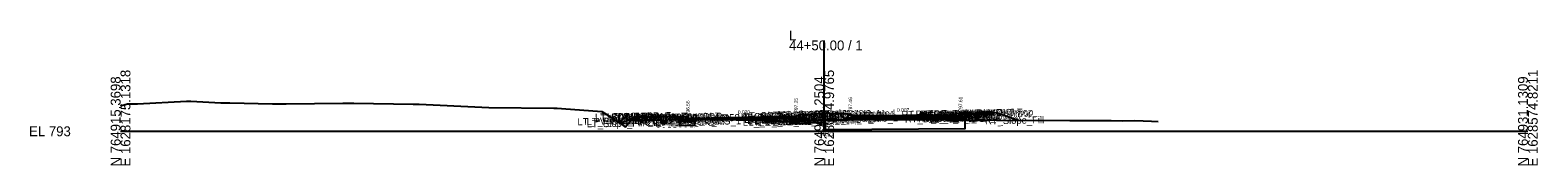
# Model space of a CAD drawing. Extents: x -26 to 4403, y -510 to 9556.
# Drawn here: x 2974.3 to 3402.8, y 4490.3 to 4528.6 of the extents above; entities that cross this region are included whole.
import ezdxf

# ---------------------------------------------------------------- set-up
doc = ezdxf.new("R2010")
doc.units = 0
for name, color, linetype in [('Default', 7, 'Continuous'), ('Exist CMT Pavement', 7, 'Continuous'), ('Exist Cross Section Cell', 7, 'Continuous'), ('Exist XS Center Line Elevation Label', 7, 'Continuous'), ('Exist XS Ground Line', 7, 'Continuous'), ('Prop CMT Conc Surface', 7, 'Continuous'), ('Prop CMT Concrete Structures', 7, 'Continuous'), ('Prop CMT Pvmt Course 1', 7, 'Continuous'), ('Prop CMT Pvmt Course 1 CG', 7, 'Continuous'), ('Prop CMT Pvmt Course 2', 7, 'Continuous'), ('Prop CMT Pvmt Course 2 Wedge', 7, 'Continuous'), ('Prop CMT Pvmt Course 3', 7, 'Continuous'), ('Prop CMT Pvmt Course 3 Wedge', 7, 'Continuous'), ('Prop CMT Pvmt Surface', 7, 'Continuous'), ('Prop CMT Shallow Undercut', 7, 'Continuous'), ('Prop CMT Shallow Undercut Boundary', 7, 'Continuous'), ('Prop CMT Slope Grass', 7, 'Continuous'), ('Prop CMT Subgrade Earthwork', 7, 'Continuous'), ('Prop CMT Undercut Boundary', 7, 'Continuous'), ('Prop XS Hydro Elevations', 7, 'Continuous'), ('Prop XS SE Text', 7, 'Continuous'), ('Prop XS Side Slope Text', 7, 'Continuous'), ('Scratch_Level_0', 7, 'Continuous')]:
    doc.layers.add(name, color=color, linetype=linetype)

msp = doc.modelspace()

# ---------------------------------------------------------------- linework, layer by layer
at = {"layer": 'Exist CMT Pavement'}
msp.add_lwpolyline([(3163.26, 4503.34), (3171.04, 4503.32), (3179.03, 4503.16), (3182.93, 4503.07), (3185.38, 4502.99), (3190.29, 4502.83)], dxfattribs=at)
at = {"layer": 'Exist Cross Section Cell'}
for p, q in [((3200, 4500), (3200, 4525.82)), ((3000, 4500), (3200, 4500)), ((3200, 4500), (3400, 4500))]:
    msp.add_line(p, q, dxfattribs=at)
at = {"layer": 'Exist XS Ground Line'}
msp.add_lwpolyline([(3000, 4507.26), (3001.98, 4507.77), (3004.81, 4507.85), (3018.76, 4508.56), (3019.94, 4508.61), (3028.49, 4508.12), (3031.03, 4508.07), (3043.17, 4507.81), (3047.06, 4507.79), (3063.19, 4508.02), (3066.31, 4507.99), (3083.2, 4507.72), (3084.88, 4507.69), (3102.72, 4506.86), (3104.71, 4506.76), (3123.12, 4506.62), (3123.71, 4506.62), (3124.11, 4506.6), (3125.33, 4506.52), (3136.82, 4505.63), (3139.26, 4504.1), (3142.46, 4501.95), (3143.03, 4501.56), (3143.53, 4501.28), (3144.92, 4503), (3159.01, 4503.34), (3159.37, 4503.35), (3160.22, 4503.35), (3171.04, 4503.32), (3179.03, 4503.16), (3182.93, 4503.07), (3185.38, 4502.99), (3190.29, 4502.83), (3192.5, 4502.88), (3198.36, 4503.2), (3200, 4503.21), (3206.75, 4503.28), (3213.59, 4503.32), (3219.88, 4503.32), (3249, 4503.16), (3269.81, 4503.1), (3281.61, 4503.05), (3284.9, 4503.01), (3288.31, 4503.04), (3293.04, 4502.89), (3294.96, 4502.83)], dxfattribs=at)
at = {"layer": 'Prop CMT Conc Surface'}
for points in [[(3153.63, 4504.2), (3148.63, 4504.3)], [(3161.25, 4503.55), (3161.25, 4504.05), (3160.75, 4504.05)], [(3191.25, 4504.23), (3192, 4504.25), (3192, 4504.41), (3192.76, 4504.66)], [(3208.19, 4504.47), (3207.44, 4504.46), (3207.44, 4504.63), (3206.68, 4504.88)], [(3236.75, 4504.67), (3238.75, 4504.61)], [(3238.75, 4504.61), (3238.75, 4505.11), (3239.25, 4505.11)], [(3243.25, 4505.2), (3248.25, 4505.3)], [(3163.25, 4503.67), (3161.25, 4503.55)]]:
    msp.add_lwpolyline(points, dxfattribs=at)
at = {"layer": 'Prop CMT Concrete Structures'}
for points in [[(3148.63, 4503.97), (3148.63, 4504.3)], [(3148.63, 4504.3), (3153.63, 4504.2)], [(3153.63, 4503.87), (3148.63, 4503.97)], [(3153.63, 4504.2), (3153.63, 4503.87)], [(3163.25, 4503.67), (3161.25, 4503.55), (3161.25, 4504.05), (3160.75, 4504.05)], [(3160.75, 4504.05), (3160.75, 4503.04), (3163.25, 4503.09)], [(3191.25, 4504.23), (3192, 4504.25), (3192, 4504.41), (3192.76, 4504.66)], [(3191.25, 4503.65), (3191.25, 4504.23)], [(3192.76, 4504.66), (3192.76, 4503.68)], [(3208.19, 4504.47), (3207.44, 4504.46), (3207.44, 4504.63), (3206.68, 4504.88)], [(3206.68, 4504.88), (3206.68, 4503.87)], [(3206.68, 4503.87), (3208.19, 4503.88)], [(3208.19, 4503.88), (3208.19, 4504.47)], [(3236.75, 4504.67), (3238.75, 4504.61), (3238.75, 4505.11), (3239.25, 4505.11)], [(3239.25, 4505.11), (3239.25, 4504.11), (3236.75, 4504.09)], [(3236.75, 4504.09), (3236.75, 4504.67)], [(3248.25, 4505.3), (3243.25, 4505.2)], [(3243.25, 4505.2), (3243.25, 4504.87)], [(3243.25, 4504.87), (3248.25, 4504.97)], [(3248.25, 4504.97), (3248.25, 4505.3)], [(3163.25, 4503.09), (3163.25, 4503.67)], [(3192.76, 4503.68), (3191.25, 4503.65)]]:
    msp.add_lwpolyline(points, dxfattribs=at)
at = {"layer": 'Prop CMT Pvmt Course 1'}
for points in [[(3191.25, 4504.23), (3163.25, 4503.67)], [(3163.25, 4503.42), (3190.29, 4503.96), (3191.25, 4503.98)], [(3191.25, 4503.98), (3191.25, 4504.23)], [(3208.19, 4504.47), (3236.75, 4504.67)], [(3208.19, 4504.22), (3208.19, 4504.47)], [(3236.75, 4504.42), (3208.19, 4504.22)], [(3208.19, 4504.22), (3208.19, 4504.22), (3208.19, 4504.22)], [(3236.75, 4504.67), (3236.75, 4504.42)], [(3163.25, 4503.67), (3163.25, 4503.42), (3163.25, 4503.42)]]:
    msp.add_lwpolyline(points, dxfattribs=at)
at = {"layer": 'Prop CMT Pvmt Course 1 CG'}
for points in [[(3208.19, 4503.88), (3206.18, 4503.87), (3205.84, 4503.53)], [(3208.19, 4503.55), (3208.19, 4503.88)], [(3236.75, 4504.09), (3239.75, 4504.11), (3240.08, 4503.78)], [(3236.75, 4503.76), (3236.75, 4504.09)], [(3163.25, 4503.09), (3160.25, 4503.03), (3159.91, 4502.69)], [(3159.91, 4502.69), (3163.25, 4502.76)], [(3163.25, 4502.76), (3163.25, 4503.09)], [(3191.25, 4503.65), (3193.26, 4503.69), (3193.59, 4503.36)], [(3191.25, 4503.32), (3191.25, 4503.65)], [(3193.59, 4503.36), (3191.25, 4503.32)], [(3205.84, 4503.53), (3208.19, 4503.55)], [(3240.08, 4503.78), (3236.75, 4503.76)]]:
    msp.add_lwpolyline(points, dxfattribs=at)
at = {"layer": 'Prop CMT Pvmt Course 2'}
for points in [[(3191.25, 4503.98), (3190.29, 4503.96)], [(3190.29, 4503.96), (3190.29, 4503.63)], [(3191.25, 4503.65), (3191.25, 4503.98)], [(3208.19, 4504.22), (3236.75, 4504.42)], [(3208.19, 4503.88), (3208.19, 4504.22)], [(3236.75, 4504.09), (3208.19, 4503.88)], [(3236.75, 4504.42), (3236.75, 4504.09)], [(3163.25, 4503.09), (3163.25, 4503.09), (3163.25, 4503.42), (3163.25, 4503.42)], [(3163.25, 4503.42), (3163.25, 4503.09)], [(3190.29, 4503.63), (3191.25, 4503.65)]]:
    msp.add_lwpolyline(points, dxfattribs=at)
at = {"layer": 'Prop CMT Pvmt Course 2 Wedge'}
for points in [[(3163.25, 4503.42), (3171.04, 4503.58), (3179.03, 4503.74), (3182.93, 4503.82), (3185.38, 4503.87), (3190.29, 4503.96)], [(3190.29, 4503.96), (3190.29, 4503.63)], [(3190.29, 4503.63), (3185.38, 4503.53), (3182.93, 4503.48), (3179.03, 4503.41), (3172.87, 4503.28), (3171.04, 4503.32), (3163.25, 4503.34)], [(3163.25, 4503.34), (3163.25, 4503.42)]]:
    msp.add_lwpolyline(points, dxfattribs=at)
at = {"layer": 'Prop CMT Pvmt Course 3'}
for points in [[(3208.19, 4503.88), (3236.75, 4504.09)], [(3208.19, 4503.55), (3208.19, 4503.88)], [(3236.75, 4504.09), (3236.75, 4503.76)], [(3163.25, 4503.09), (3163.25, 4503.09), (3163.25, 4502.76), (3163.25, 4502.76)], [(3163.25, 4502.76), (3163.25, 4503.09)], [(3191.25, 4503.65), (3190.29, 4503.63)], [(3190.29, 4503.63), (3190.29, 4503.3)], [(3190.29, 4503.3), (3191.25, 4503.32)], [(3191.25, 4503.32), (3191.25, 4503.65)], [(3236.75, 4503.76), (3208.19, 4503.55)]]:
    msp.add_lwpolyline(points, dxfattribs=at)
at = {"layer": 'Prop CMT Pvmt Course 3 Wedge'}
for points in [[(3172.87, 4503.28), (3179.03, 4503.41)], [(3190.29, 4502.83), (3185.38, 4502.99), (3182.93, 4503.07), (3179.03, 4503.16), (3172.87, 4503.28)], [(3179.03, 4503.41), (3182.93, 4503.48), (3185.38, 4503.53), (3190.29, 4503.63)], [(3190.29, 4503.63), (3190.29, 4502.83)]]:
    msp.add_lwpolyline(points, dxfattribs=at)
at = {"layer": 'Prop CMT Pvmt Surface'}
for points in [[(3191.25, 4504.23), (3163.25, 4503.67)], [(3208.19, 4504.47), (3236.75, 4504.67)]]:
    msp.add_lwpolyline(points, dxfattribs=at)
at = {"layer": 'Prop CMT Shallow Undercut'}
for points in [[(3158.91, 4502.67), (3158.91, 4501.67), (3163.25, 4501.76), (3163.25, 4502.76)], [(3190.29, 4502.83), (3190.29, 4502.32), (3200.29, 4502.46), (3200.29, 4503.22), (3199.18, 4503.2), (3198.36, 4503.2), (3193.97, 4502.96), (3192.5, 4502.88), (3191.4, 4502.85)]]:
    msp.add_lwpolyline(points, close=True, dxfattribs=at)
at = {"layer": 'Prop CMT Shallow Undercut Boundary'}
for points in [[(3158.91, 4502.67), (3158.91, 4501.67), (3163.25, 4501.76), (3163.25, 4502.76)], [(3190.29, 4502.83), (3190.29, 4502.32), (3200.29, 4502.46), (3200.29, 4503.22), (3199.18, 4503.2), (3198.36, 4503.2), (3195.43, 4503.04), (3192.5, 4502.88), (3191.4, 4502.85)]]:
    msp.add_lwpolyline(points, close=True, dxfattribs=at)
at = {"layer": 'Prop CMT Slope Grass'}
for points in [[(3160.75, 4504.05), (3148.11, 4504.31), (3141.99, 4502.27)], [(3192.76, 4504.66), (3199.72, 4505.02)], [(3206.68, 4504.88), (3199.72, 4505.02)], [(3239.25, 4505.11), (3248.75, 4505.3), (3255.23, 4503.14)]]:
    msp.add_lwpolyline(points, dxfattribs=at)
at = {"layer": 'Prop CMT Subgrade Earthwork'}
for points in [[(3163.25, 4502.76), (3159.91, 4502.69), (3158.5, 4504.1)], [(3195, 4504.78), (3193.59, 4503.36)], [(3204.45, 4504.92), (3205.84, 4503.53)], [(3236.75, 4503.76), (3240.08, 4503.78), (3241.45, 4505.15)], [(3163.25, 4502.76), (3163.26, 4503.34)], [(3163.25, 4502.76), (3163.25, 4503.09)], [(3163.25, 4502.76), (3163.25, 4502.76)], [(3163.25, 4502.76), (3163.25, 4502.76)], [(3191.25, 4503.32), (3190.29, 4503.3)], [(3190.29, 4503.3), (3190.29, 4502.83)], [(3193.59, 4503.36), (3191.25, 4503.32)], [(3191.25, 4503.32), (3191.25, 4503.32)], [(3205.84, 4503.53), (3208.19, 4503.55)], [(3208.19, 4503.55), (3236.75, 4503.76)], [(3208.19, 4503.55), (3208.19, 4503.55)], [(3208.19, 4503.55), (3208.19, 4503.55)], [(3236.75, 4503.76), (3236.75, 4503.76)]]:
    msp.add_lwpolyline(points, dxfattribs=at)
at = {"layer": 'Prop CMT Undercut Boundary'}
msp.add_lwpolyline([(3200.29, 4503.22), (3200.29, 4500.49), (3240.08, 4500.78), (3240.08, 4503.21), (3228.2, 4503.27), (3219.88, 4503.32), (3212.86, 4503.31), (3206.75, 4503.28), (3202.8, 4503.24)], close=True, dxfattribs=at)

# ---------------------------------------------------------------- texts
at = {"layer": 'Default'}
msp.add_text('-', height=0.0001, dxfattribs=at).set_placement((3000, 4500))
at = {"layer": 'Exist Cross Section Cell'}
for s, p in [('44+50.00 / 1', (3190, 4523.02)), ('L', (3190, 4525.82)), ('EL 793', (2974, 4498.6))]:
    msp.add_text(s, height=2.8, dxfattribs=at).set_placement(p)
for s, p in [('E 1628175.1318', (3002.8, 4490)), ('E 1628374.9765', (3202.8, 4490)), ('E 1628574.8211', (3402.8, 4490)), ('N 764915.3698', (3000, 4490)), ('N 764923.2504', (3200, 4490)), ('N 764931.1309', (3400, 4490))]:
    msp.add_text(s, height=2.8, rotation=90, dxfattribs=at).set_placement(p)
at = {"layer": 'Exist XS Center Line Elevation Label'}
msp.add_text('796.21', height=1.2, dxfattribs=at).set_placement((3197.72, 4498.61))
at = {"layer": 'Prop XS Hydro Elevations'}
for s, p in [('796.55', (3161.75, 4504.55)), ('797.25', (3192.5, 4505.25)), ('797.46', (3207.94, 4505.46)), ('797.61', (3239.25, 4505.61))]:
    msp.add_text(s, height=1, rotation=90, dxfattribs=at).set_placement(p)
at = {"layer": 'Prop XS SE Text'}
for s, rotation, p in [('0.020', 1.1458, (3175.48, 4504.92)), ('0.007', 0.4152, (3220.71, 4505.56))]:
    msp.add_text(s, height=1, rotation=rotation, dxfattribs=at).set_placement(p)
at = {"layer": 'Prop XS Side Slope Text'}
for rotation, p in [(18.4356, (3144.06, 4503.75)), (341.5679, (3251.48, 4505.18))]:
    msp.add_text('3:1', height=1, rotation=rotation, dxfattribs=at).set_placement(p)
at = {"layer": 'Scratch_Level_0'}
for s, p in [('LT_PV_Sub_Tie_Out', (3129.89, 4501.7)), ('LT_PV_OEEOP_EG', (3132.49, 4501.76)), ('LT_SDWK_Out_Top', (3134.89, 4503.03)), ('LT_SDWK_Out_Bot', (3134.92, 4502.7)), ('LT_CSLP_Pnt', (3138.3, 4503.11)), ('LT_Sub_Trench_Out_DLT', (3139.09, 4502.71)), ('44+50.00', (3141.61, 4503.17)), ('LT_SDWK_In_Top', (3141.52, 4502.96)), ('LT_SDWK_In_Bot', (3141.55, 4502.63)), ('LT_CG1_Shelf_Out', (3146.82, 4501.76)), ('LT_CG_Top_Face', (3148.53, 4502.8)), ('LT_CG_Top_BOC', (3149.05, 4502.82)), ('LT_CG_Bot_BOC', (3149.09, 4501.81)), ('LT_Sub_OEOT_CG_1', (3149.49, 4501.48)), ('LT_CG_Top_Gut', (3149.51, 4502.32)), ('LT_Sub_OEEOP', (3152.48, 4501.54)), ('LT_PV2_OEEOP', (3152.58, 4502.21)), ('LT_PV3_OEEOP', (3152.58, 4501.88)), ('44+50.00', (3152.83, 4502.94)), ('LT_CG_Bot_IE', (3153.19, 4501.89)), ('LT_Sub_OEOT', (3153.35, 4501.56)), ('LT_PV2_OEOT', (3153.45, 4502.23)), ('LT_PV3_OEOT', (3153.45, 4501.89)), ('LT_PV1_OEOT', (3154.01, 4502.49)), ('44+50.00', (3154.17, 4502.92)), ('44+50.00', (3154.52, 4502.66)), ('44+50.00', (3155.72, 4502.49)), ('44+50.00', (3168.51, 4502.78)), ('LT_CG_Top_Face_Med', (3175.39, 4503.08)), ('LT_CG_Top_Gut_Med', (3176.37, 4502.94)), ('LT_PV_Sub_Tie_In', (3176.88, 4501.56)), ('LT_CG_Top_BOC_Med', (3177.18, 4503.35)), ('LT_CG_Bot_BOC_Med', (3177.21, 4502.37)), ('LT_CG_Bot_IE_Med', (3177.34, 4502.37)), ('LT_Sub_IEOT_CG_1', (3178.14, 4502.05)), ('LT_PV_IEEOP_EG', (3178.5, 4501.6)), ('LT_Sub_IEEOP', (3180.17, 4502.09)), ('LT_PV2_IEEOP', (3180.26, 4502.76)), ('LT_PV3_IEEOP', (3180.26, 4502.43)), ('LT_CG1_Shelf_In', (3181.46, 4502.45)), ('LT_Sub_PGL', (3182.39, 4502.14)), ('LT_PV2_PGL', (3182.48, 4502.81)), ('LT_PV3_PGL', (3182.48, 4502.47)), ('LT_PV1_PGL', (3183.05, 4503.07)), ('LT_Sub_DLT_In', (3183.97, 4503.56)), ('LT_Sub_IEOP', (3184.36, 4502.18)), ('44+50.00', (3185.06, 4503.11)), ('MD_Crown Point', (3186.81, 4503.76)), ('RT_CG_Top_Face_Med', (3190.78, 4503.29)), ('RT_CG_Top_BOC_Med', (3191.05, 4503.57)), ('RT_CG_Bot_BOC_Med', (3191.08, 4502.56)), ('RT_CG_Top_Gut_Med', (3191.76, 4503.15)), ('RT_Sub_DLT_In', (3193.37, 4503.7)), ('RT_CG_Bot_IE_Med', (3194.22, 4502.6)), ('RT_CG1_Shelf_In', (3194.32, 4502.63)), ('RT_Sub_IEOT_CG_1', (3195.03, 4502.29)), ('44+50.00', (3195.38, 4503.83)), ('RT_Sub_IEOP', (3196.57, 4502.35)), ('RT_Sub_OEEOP', (3197.37, 4502.33)), ('RT_PV2_OEEOP', (3197.47, 4503)), ('RT_PV3_OEEOP', (3197.47, 4502.67)), ('RT_Sub_IEEOP', (3198.02, 4502.35)), ('RT_PV2_IEEOP', (3198.11, 4503.02)), ('44+50.00', (3198.58, 4503.77)), ('RT_Sub_PGL', (3199.28, 4502.37)), ('RT_PV2_PGL', (3199.37, 4503.04)), ('RT_PV1_PGL', (3199.94, 4503.3)), ('44+50.00', (3201.3, 4503.33)), ('44+50.00', (3206.64, 4503.37)), ('RT_Sub_Trench_Out_DLT', (3222, 4503.76)), ('RT_Sub_OEOT_CG_1', (3222.95, 4502.48)), ('RT_CG_Top_Face', (3225.99, 4503.85)), ('RT_CG1_Shelf_Out', (3226.28, 4502.84)), ('RT_CG_Bot_IE', (3226.64, 4502.89)), ('RT_Sub_OEOT', (3226.8, 4502.56)), ('RT_PV2_OEOT', (3226.9, 4503.23)), ('RT_PV3_OEOT', (3226.9, 4502.89)), ('RT_CG_Top_Gut', (3226.96, 4503.37)), ('RT_PV1_OEOT', (3227.46, 4503.49)), ('RT_CG_Top_BOC', (3227.51, 4503.87)), ('RT_CG_Bot_BOC', (3227.54, 4502.87)), ('RT_Sub_OEOP', (3230.17, 4502.58)), ('RT_SDWK_In_Top', (3231.08, 4503.95)), ('RT_SDWK_In_Bot', (3231.12, 4503.62)), ('44+50.00', (3232.44, 4503.97)), ('RT_SDWK_Out_Top', (3234.46, 4504.02)), ('RT_SDWK_Out_Bot', (3234.49, 4503.69)), ('RT_CSLP_Pnt', (3238.9, 4504.1)), ('44+50.00', (3241.84, 4504.16)), ('44+50.00', (3244.66, 4503.28)), ('RT_Slope_Fill', (3245.73, 4501.95)), ('LT_Slope_Fill', (3132.53, 4501.08)), ('LT_Sub_OEOP', (3150.04, 4501.49))]:
    msp.add_text(s, height=2, rotation=1.1458, dxfattribs=at).set_placement(p)

doc.saveas('drawing.dxf')
